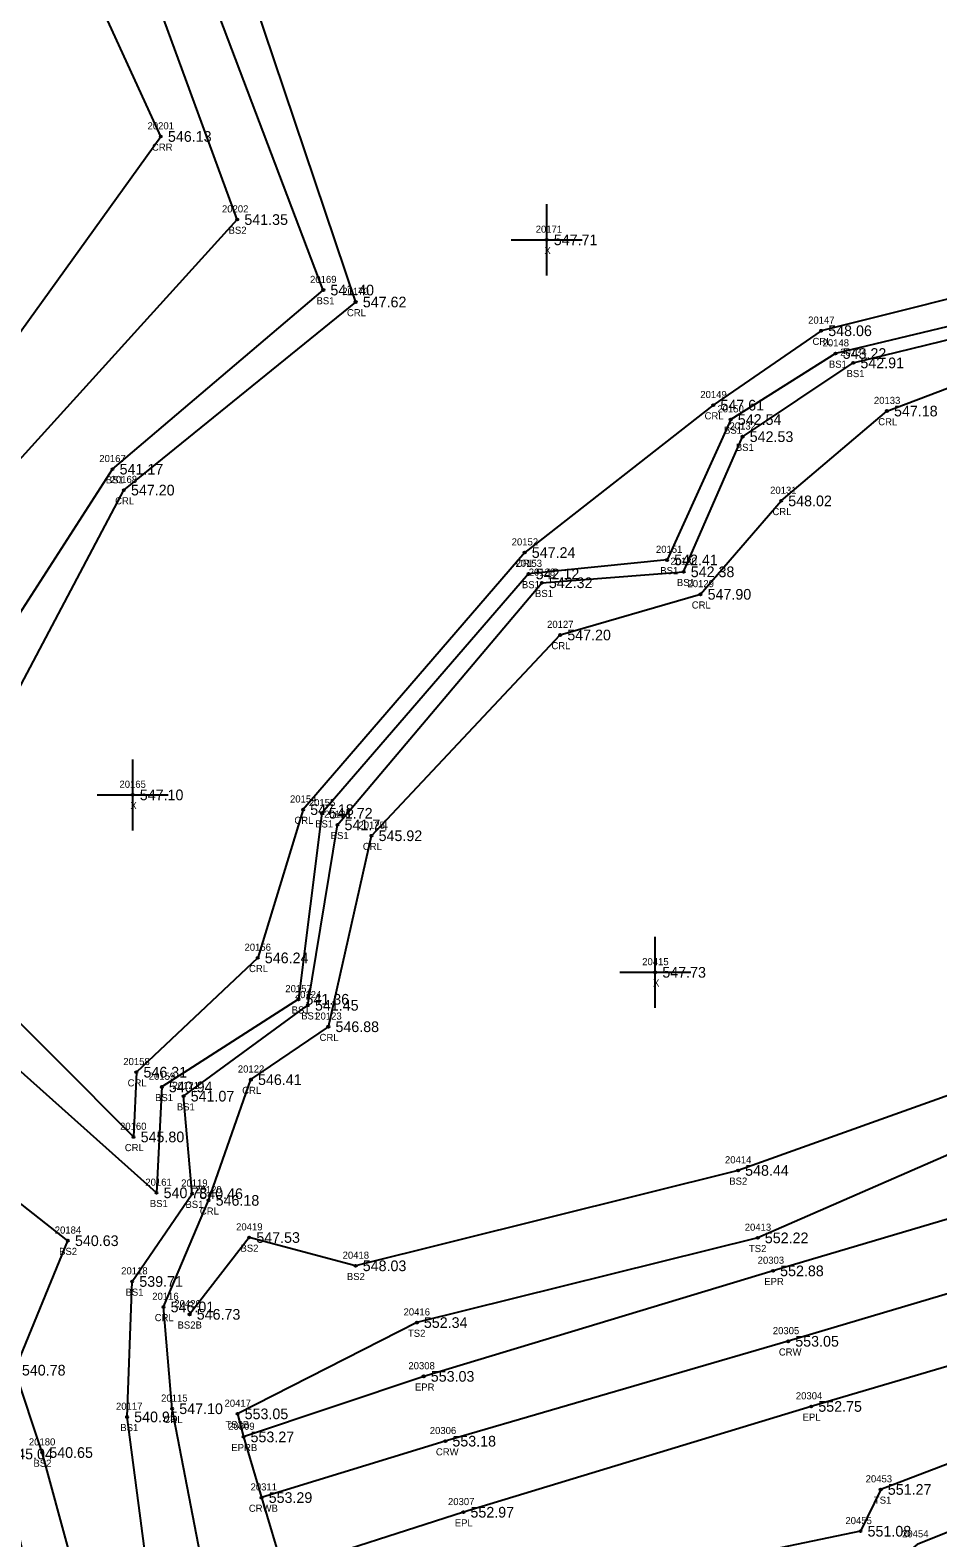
# Model space of a CAD drawing. Extents: x 1540443 to 1541844, y 887157 to 888162.
# Drawn here: x 1541136.9 to 1541264.6, y 887681.2 to 887893.1 of the extents above; entities that cross this region are included whole.
import ezdxf

# ---------------------------------------------------------------- set-up
doc = ezdxf.new("R2010")
doc.units = 0
for name, color, linetype in [('RD_DTM_BkLn1', 7, 'Continuous'), ('RD_DTM_BkLn2', 7, 'Continuous'), ('RD_DTM_BkLn_txCode', 7, 'Continuous'), ('RD_EX_H2O', 7, 'Continuous'), ('RD_EX_H2O_txCode', 7, 'Continuous'), ('RD_EX_Misc', 7, 'Continuous'), ('RD_EX_Misc_txCode', 7, 'Continuous'), ('RD_EX_Road', 7, 'Continuous'), ('RD_EX_Road_txCode', 7, 'Continuous'), ('RD_EX_TX_H2O_ELEV', 7, 'Continuous'), ('RD_EX_TX_Misc_ELEV', 7, 'Continuous'), ('RD_EX_TX_Road_ELEV', 7, 'Continuous'), ('RD_HC_Survey_ELEV', 7, 'Continuous'), ('RD_HC_Survey_txCode', 7, 'Continuous'), ('RD_SMD_Locator', 7, 'Continuous')]:
    doc.layers.add(name, color=color, linetype=linetype)

msp = doc.modelspace()

# ---------------------------------------------------------------- linework, layer by layer
at = {"layer": 'RD_DTM_BkLn1'}
msp.add_lwpolyline([(1541819.64, 887879.04), (1541771.84, 887865.01), (1541723.55, 887850.95), (1541675.82, 887836.26), (1541627.89, 887822.08), (1541580.01, 887807.87), (1541531.93, 887793.38), (1541484.13, 887778.91), (1541435.66, 887765.21), (1541388.1, 887751.04), (1541339.55, 887736.89), (1541291.46, 887723.08), (1541243.5, 887708.82), (1541195.27, 887694.78), (1541169.43, 887686.85)], dxfattribs=at)
at = {"layer": 'RD_DTM_BkLn2'}
for points in [[(1541349.06, 887859.41), (1541301.9, 887838.51), (1541276.98, 887854.12), (1541250.17, 887847.68), (1541235.42, 887838.4), (1541226.46, 887818.66), (1541206.99, 887816.69), (1541177.91, 887783.05), (1541174.61, 887756.9), (1541155.39, 887744.58), (1541154.65, 887729.69), (1541126.74, 887754.56), (1541108.32, 887769.11), (1541148.46, 887831.42), (1541178.11, 887856.6), (1541159.66, 887905.22), (1541133.37, 887953.98), (1541101.85, 887998.23), (1541093.93, 888039.66), (1541072.92, 888058.86), (1541087, 888085), (1541104.04, 888122.31), (1541088.02, 888158.63)], [(1541146.1, 887665.49), (1541138.57, 887693.18), (1541134.72, 887704.76), (1541142.18, 887722.96), (1541114.88, 887744.39), (1541098.19, 887760.21), (1541108.65, 887794.85), (1541126.24, 887822.69), (1541166.01, 887866.51), (1541149.08, 887912.73), (1541115.84, 887949.01), (1541089.41, 887986.26), (1541082.08, 888036.68), (1541064.88, 888057.53), (1541079.32, 888092.84), (1541092.39, 888127.26), (1541076.18, 888157.56)], [(1541824.97, 887864.95), (1541773.24, 887848.9), (1541728.33, 887834.59), (1541680.22, 887820.65), (1541632.2, 887806.6), (1541586.15, 887794.2), (1541535.56, 887777.78), (1541490.03, 887763.87), (1541442.11, 887749.28), (1541414.74, 887732.66), (1541394.55, 887728.51), (1541346.01, 887715.56), (1541298.68, 887704.05), (1541256.52, 887687.99), (1541253.67, 887682.12), (1541204.18, 887671.81), (1541185.24, 887668.7), (1541173.43, 887674.53)], [(1541826.01, 887862.16), (1541773.99, 887846.34), (1541729.05, 887832.97), (1541681.03, 887818.46), (1541632.94, 887804.51), (1541587.44, 887789.41), (1541536.78, 887773.27), (1541491.06, 887758.08), (1541445.99, 887740.14), (1541416.24, 887728.45), (1541395.49, 887723.75), (1541347.04, 887711.22), (1541300.85, 887696.02), (1541261.64, 887680.26), (1541255.59, 887675.42), (1541206.42, 887663.07), (1541174, 887652.79)], [(1541154.57, 887667.56), (1541150.51, 887698.19), (1541151.23, 887717.23), (1541159.67, 887729.57), (1541158.46, 887743.28), (1541175.94, 887756.06), (1541180.1, 887781.42), (1541208.84, 887815.45), (1541228.8, 887816.99), (1541237.09, 887835.99), (1541252.66, 887846.36), (1541275.47, 887851.95), (1541302.69, 887835.08), (1541351.22, 887857.05)], [(1541364.55, 887796.04), (1541367.46, 887774.49), (1541335.06, 887766.51), (1541282.53, 887749.29), (1541236.45, 887732.84), (1541182.66, 887719.43), (1541167.69, 887723.41), (1541159.31, 887712.61)], [(1541364.55, 887796.04), (1541374.72, 887771.14), (1541336.02, 887760.2), (1541284.5, 887743.07), (1541239.22, 887723.36), (1541191.26, 887711.45), (1541166.05, 887698.62)], [(1541166.05, 887698.62), (1541166.88, 887695.38), (1541169.43, 887686.85), (1541172.48, 887676.63), (1541173.43, 887674.53)]]:
    msp.add_lwpolyline(points, dxfattribs=at)
at = {"layer": 'RD_EX_H2O'}
for points in [[(1541345.47, 887860.33), (1541299.81, 887843.04), (1541278.31, 887858.39), (1541248.14, 887850.88), (1541232.97, 887840.42), (1541206.44, 887819.7), (1541175.27, 887783.56), (1541168.89, 887762.72), (1541151.82, 887746.65), (1541151.42, 887737.55), (1541129.57, 887759.43), (1541125.03, 887781.17), (1541150.06, 887828.48), (1541182.67, 887854.92), (1541164.01, 887910.29), (1541139.24, 887954.07), (1541111.52, 888003.47), (1541100.67, 888047.04), (1541091.5, 888080.23), (1541107.64, 888120.67), (1541095.14, 888160.09)], [(1541139.32, 887662.55), (1541132.94, 887692.98), (1541127.99, 887710.83), (1541127.84, 887719.69), (1541112.29, 887736.27), (1541094.28, 887759.52), (1541097.04, 887797.31), (1541106.04, 887811.91), (1541109.47, 887816.01), (1541121.03, 887830.67), (1541155.26, 887878.19), (1541140.59, 887910.22), (1541112.01, 887944.26), (1541086.28, 887983.65), (1541077.88, 888035.59), (1541062.25, 888056.78), (1541074.93, 888096.19), (1541086.66, 888128.26), (1541074.68, 888157.66)], [(1541162.66, 887669.25), (1541156.85, 887699.34), (1541155.63, 887713.65), (1541161.97, 887728.63), (1541167.93, 887745.6), (1541178.82, 887753.04), (1541184.89, 887779.89), (1541211.43, 887808.11), (1541231.17, 887813.83), (1541242.51, 887826.96), (1541257.39, 887839.59), (1541274.43, 887846.05), (1541301.1, 887832.19), (1541353.26, 887851.5)]]:
    msp.add_lwpolyline(points, dxfattribs=at)
at = {"layer": 'RD_EX_Misc'}
for p, q in [((1541209.54, 887858.66), (1541209.54, 887868.66)), ((1541204.54, 887863.66), (1541214.54, 887863.66)), ((1541151.3, 887780.63), (1541151.3, 887790.63)), ((1541146.3, 887785.63), (1541156.3, 887785.63)), ((1541224.8, 887755.69), (1541224.8, 887765.69)), ((1541219.8, 887760.69), (1541229.8, 887760.69))]:
    msp.add_line(p, q, dxfattribs=at)
at = {"layer": 'RD_EX_Road'}
for points in [[(1541816.45, 887889.18), (1541769.26, 887875.17), (1541720.7, 887860.02), (1541673.15, 887846.35), (1541624.52, 887832.03), (1541577.1, 887817.68), (1541529.45, 887803.59), (1541481.09, 887788.89), (1541433.23, 887775.3), (1541384.84, 887760.56), (1541337.12, 887746.96), (1541288.35, 887732.65), (1541241.37, 887718.72), (1541192.23, 887703.89), (1541166.88, 887695.38)], [(1541823.08, 887870.08), (1541774.23, 887855.6), (1541726.64, 887841.16), (1541678.89, 887827.09), (1541630.15, 887812.57), (1541582.93, 887798.43), (1541534.59, 887784.1), (1541487.04, 887769.99), (1541438.64, 887755.66), (1541391.44, 887742.05), (1541342.36, 887727.48), (1541295.07, 887713.91), (1541246.74, 887699.66), (1541197.81, 887684.79), (1541172.48, 887676.63)]]:
    msp.add_lwpolyline(points, dxfattribs=at)
at = {"layer": 'RD_SMD_Locator'}
for centre in [(1541155.26, 887878.19), (1541166.01, 887866.51), (1541209.54, 887863.66), (1541178.11, 887856.6), (1541182.67, 887854.92), (1541248.14, 887850.88), (1541250.17, 887847.68), (1541252.66, 887846.36), (1541232.97, 887840.42), (1541235.42, 887838.4), (1541257.39, 887839.59), (1541237.09, 887835.99), (1541148.46, 887831.42), (1541150.06, 887828.48), (1541242.51, 887826.96), (1541206.44, 887819.7), (1541206.99, 887816.69), (1541226.46, 887818.66), (1541228.8, 887816.99), (1541208.84, 887815.45), (1541231.17, 887813.83), (1541211.43, 887808.11), (1541151.3, 887785.63), (1541175.27, 887783.56), (1541177.91, 887783.05), (1541180.1, 887781.42), (1541184.89, 887779.89), (1541168.89, 887762.72), (1541224.8, 887760.69), (1541174.61, 887756.9), (1541175.94, 887756.06), (1541178.82, 887753.04), (1541151.82, 887746.65), (1541155.39, 887744.58), (1541167.93, 887745.6), (1541158.46, 887743.28), (1541151.42, 887737.55), (1541236.45, 887732.84), (1541154.65, 887729.69), (1541159.67, 887729.57), (1541161.97, 887728.63), (1541167.69, 887723.41), (1541239.22, 887723.36), (1541142.18, 887722.96), (1541182.66, 887719.43), (1541151.23, 887717.23), (1541241.37, 887718.72), (1541155.63, 887713.65), (1541159.31, 887712.61), (1541191.26, 887711.45), (1541243.5, 887708.82), (1541192.23, 887703.89), (1541150.51, 887698.19), (1541156.85, 887699.34), (1541166.05, 887698.62), (1541246.74, 887699.66), (1541166.88, 887695.38), (1541195.27, 887694.78), (1541138.57, 887693.18), (1541256.52, 887687.99), (1541169.43, 887686.85), (1541197.81, 887684.79), (1541253.67, 887682.12)]:
    msp.add_circle(centre, 0.15, dxfattribs=at)

# ---------------------------------------------------------------- texts
at = {"layer": 'RD_DTM_BkLn_txCode'}
for s, p in [('20202', (1541163.86, 887867.51)), ('BS2', (1541164.79, 887864.51)), ('20169', (1541176.25, 887857.6)), ('BS1', (1541177.16, 887854.6)), ('20148', (1541248.34, 887848.68)), ('BS1', (1541249.23, 887845.68)), ('20134', (1541250.82, 887847.36)), ('BS1', (1541251.71, 887844.36)), ('20150', (1541233.55, 887839.4)), ('20132', (1541235.25, 887836.99)), ('BS1', (1541234.48, 887836.4)), ('BS1', (1541236.14, 887833.99)), ('20167', (1541146.6, 887832.42)), ('BS1', (1541147.52, 887829.42)), ('20151', (1541224.9, 887819.66)), ('20130', (1541226.93, 887817.99)), ('20153', (1541205.16, 887817.69)), ('20128', (1541207.01, 887816.45)), ('BS1', (1541225.51, 887816.66)), ('BS1', (1541206.05, 887814.69)), ('BS1', (1541227.85, 887814.99)), ('BS1', (1541207.89, 887813.45)), ('20155', (1541176.08, 887784.05)), ('20126', (1541178.24, 887782.42)), ('BS1', (1541176.97, 887781.05)), ('BS1', (1541179.15, 887779.42)), ('20157', (1541172.77, 887757.9)), ('20124', (1541174.11, 887757.06)), ('BS1', (1541173.66, 887754.9)), ('BS1', (1541175, 887754.06)), ('20159', (1541153.56, 887745.58)), ('20121', (1541156.91, 887744.28)), ('BS1', (1541154.45, 887742.58)), ('BS1', (1541157.51, 887741.28)), ('20414', (1541234.61, 887733.84)), ('20161', (1541153.08, 887730.69)), ('20119', (1541158.12, 887730.57)), ('BS2', (1541235.22, 887730.84)), ('BS1', (1541153.71, 887727.69)), ('BS1', (1541158.72, 887727.57)), ('20184', (1541140.34, 887723.96)), ('20419', (1541165.85, 887724.41)), ('20413', (1541237.39, 887724.36)), ('BS2', (1541140.95, 887720.96)), ('BS2', (1541166.46, 887721.41)), ('20418', (1541180.83, 887720.43)), ('TS2', (1541237.98, 887721.36)), ('20118', (1541149.68, 887718.23)), ('BS2', (1541181.43, 887717.43)), ('BS1', (1541150.29, 887715.23)), ('20420', (1541157.16, 887713.61)), ('20416', (1541189.4, 887712.45)), ('BS2B', (1541157.61, 887710.61)), ('TS2', (1541190.02, 887709.45)), ('20117', (1541148.95, 887699.19)), ('20417', (1541164.22, 887699.62)), ('BS1', (1541149.56, 887696.19)), ('TS2B', (1541164.34, 887696.62)), ('20180', (1541136.7, 887694.18)), ('BS2', (1541137.34, 887691.18)), ('20453', (1541254.4, 887688.99)), ('TS1', (1541255.56, 887685.99)), ('20455', (1541251.55, 887683.12)), ('20454', (1541259.52, 887681.26))]:
    msp.add_text(s, height=1, dxfattribs=at).set_placement(p)
at = {"layer": 'RD_EX_H2O_txCode'}
for s, p in [('20201', (1541153.39, 887879.19)), ('CRR', (1541154.01, 887876.19)), ('20170', (1541180.79, 887855.92)), ('CRL', (1541181.44, 887852.92)), ('20147', (1541246.31, 887851.88)), ('CRL', (1541246.92, 887848.88)), ('20149', (1541231.14, 887841.42)), ('20133', (1541255.56, 887840.59)), ('CRL', (1541231.74, 887838.42)), ('CRL', (1541256.17, 887837.59)), ('20168', (1541148.2, 887829.48)), ('CRL', (1541148.83, 887826.48)), ('20131', (1541240.96, 887827.96)), ('CRL', (1541241.29, 887824.96)), ('20152', (1541204.61, 887820.7)), ('CRL', (1541205.21, 887817.7)), ('20129', (1541229.34, 887814.83)), ('CRL', (1541229.94, 887811.83)), ('20127', (1541209.59, 887809.11)), ('CRL', (1541210.2, 887806.11)), ('20154', (1541173.43, 887784.56)), ('CRL', (1541174.04, 887781.56)), ('20125', (1541183.06, 887780.89)), ('CRL', (1541183.67, 887777.89)), ('20156', (1541167.03, 887763.72)), ('CRL', (1541167.66, 887760.72)), ('20123', (1541176.98, 887754.04)), ('CRL', (1541177.59, 887751.04)), ('20158', (1541149.98, 887747.65)), ('20122', (1541166.09, 887746.6)), ('CRL', (1541150.59, 887744.65)), ('CRL', (1541166.7, 887743.6)), ('20160', (1541149.52, 887738.55)), ('CRL', (1541150.19, 887735.55)), ('20120', (1541160.1, 887729.63)), ('CRL', (1541160.75, 887726.63)), ('20116', (1541154.05, 887714.65)), ('CRL', (1541154.4, 887711.65)), ('20115', (1541155.3, 887700.34)), ('CRL', (1541155.63, 887697.34))]:
    msp.add_text(s, height=1, dxfattribs=at).set_placement(p)
at = {"layer": 'RD_EX_Misc_txCode'}
for s, p in [('20171', (1541207.99, 887864.66)), ('X', (1541209.22, 887861.66)), ('20165', (1541149.44, 887786.63)), ('X', (1541150.98, 887783.63)), ('20415', (1541222.97, 887761.69)), ('X', (1541224.49, 887758.69))]:
    msp.add_text(s, height=1, dxfattribs=at).set_placement(p)
at = {"layer": 'RD_EX_Road_txCode'}
for s, p in [('20303', (1541239.21, 887719.72)), ('EPR', (1541240.14, 887716.72)), ('20308', (1541190.08, 887704.89)), ('EPR', (1541191, 887701.89)), ('20304', (1541244.58, 887700.66)), ('EPL', (1541245.53, 887697.66)), ('20309', (1541164.73, 887696.38)), ('EPRB', (1541165.18, 887693.38)), ('20307', (1541195.65, 887685.79)), ('EPL', (1541196.61, 887682.79))]:
    msp.add_text(s, height=1, dxfattribs=at).set_placement(p)
at = {"layer": 'RD_EX_TX_H2O_ELEV'}
for s, p in [('546.13', (1541156.26, 887877.44)), ('547.62', (1541183.67, 887854.17)), ('548.06', (1541249.14, 887850.13)), ('547.61', (1541233.97, 887839.67)), ('547.18', (1541258.39, 887838.84)), ('547.20', (1541151.06, 887827.73)), ('548.02', (1541243.51, 887826.21)), ('547.24', (1541207.44, 887818.95)), ('547.90', (1541232.17, 887813.08)), ('547.20', (1541212.43, 887807.36)), ('547.18', (1541176.27, 887782.81)), ('545.92', (1541185.89, 887779.14)), ('546.24', (1541169.89, 887761.97)), ('546.88', (1541179.82, 887752.29)), ('546.31', (1541152.82, 887745.9)), ('546.41', (1541168.93, 887744.85)), ('545.80', (1541152.42, 887736.8)), ('546.18', (1541162.97, 887727.88)), ('546.01', (1541156.63, 887712.9)), ('547.10', (1541157.85, 887698.59)), ('545.04', (1541133.94, 887692.23))]:
    msp.add_text(s, height=1.5, dxfattribs=at).set_placement(p)
at = {"layer": 'RD_EX_TX_Misc_ELEV'}
for s, p in [('541.35', (1541167.01, 887865.76)), ('547.71', (1541210.54, 887862.91)), ('541.40', (1541179.11, 887855.85)), ('543.22', (1541251.17, 887846.93)), ('542.91', (1541253.66, 887845.61)), ('542.54', (1541236.42, 887837.65)), ('542.53', (1541238.09, 887835.24)), ('541.17', (1541149.46, 887830.67)), ('542.41', (1541227.46, 887817.91)), ('542.12', (1541207.99, 887815.94)), ('542.38', (1541229.8, 887816.24)), ('542.32', (1541209.84, 887814.7)), ('547.10', (1541152.3, 887784.88)), ('541.72', (1541178.91, 887782.3)), ('541.74', (1541181.1, 887780.67)), ('547.73', (1541225.8, 887759.94)), ('541.36', (1541175.61, 887756.15)), ('541.45', (1541176.94, 887755.31)), ('540.94', (1541156.39, 887743.83)), ('541.07', (1541159.46, 887742.53)), ('548.44', (1541237.45, 887732.09)), ('540.78', (1541155.65, 887728.94)), ('540.46', (1541160.67, 887728.82)), ('540.63', (1541143.18, 887722.21)), ('547.53', (1541168.69, 887722.66)), ('552.22', (1541240.22, 887722.61)), ('548.03', (1541183.66, 887718.68)), ('539.71', (1541152.23, 887716.48)), ('546.73', (1541160.31, 887711.86)), ('552.34', (1541192.26, 887710.7)), ('540.78', (1541135.72, 887704.01)), ('540.95', (1541151.51, 887697.44)), ('553.05', (1541167.05, 887697.87)), ('540.65', (1541139.57, 887692.43)), ('551.27', (1541257.52, 887687.24)), ('551.08', (1541254.67, 887681.37))]:
    msp.add_text(s, height=1.5, dxfattribs=at).set_placement(p)
at = {"layer": 'RD_EX_TX_Road_ELEV'}
for s, p in [('552.88', (1541242.37, 887717.97)), ('553.03', (1541193.23, 887703.14)), ('552.75', (1541247.74, 887698.91)), ('553.27', (1541167.88, 887694.63)), ('552.97', (1541198.81, 887684.04))]:
    msp.add_text(s, height=1.5, dxfattribs=at).set_placement(p)
at = {"layer": 'RD_HC_Survey_ELEV'}
for s, p in [('553.05', (1541244.5, 887708.07)), ('553.18', (1541196.27, 887694.03)), ('553.29', (1541170.43, 887686.1))]:
    msp.add_text(s, height=1.5, dxfattribs=at).set_placement(p)
at = {"layer": 'RD_HC_Survey_txCode'}
for s, p in [('20305', (1541241.34, 887709.82)), ('CRW', (1541242.19, 887706.82)), ('20306', (1541193.09, 887695.78)), ('CRW', (1541193.95, 887692.78)), ('20311', (1541167.88, 887687.85)), ('CRWB', (1541167.64, 887684.85))]:
    msp.add_text(s, height=1, dxfattribs=at).set_placement(p)

doc.saveas('drawing.dxf')
